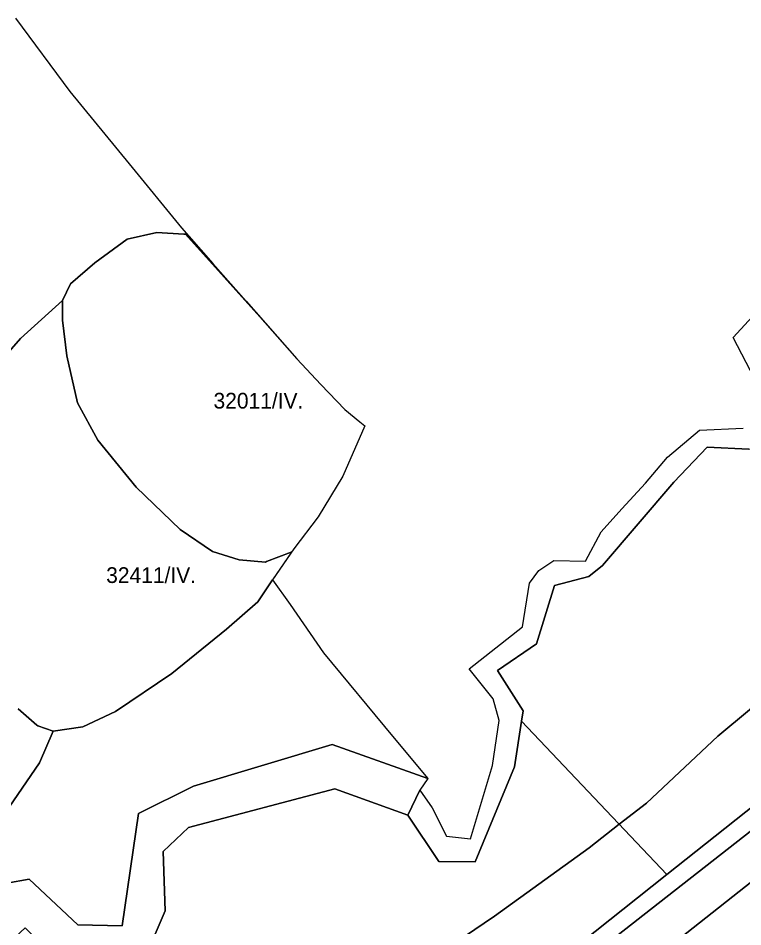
# Model space of a CAD drawing. Extents: x -522079 to -518833, y -1142400 to -1139961.
# Drawn here: x -521596.1 to -521365.3, y -1140523.8 to -1140234.6 of the extents above; entities that cross this region are included whole.
import ezdxf

# ---------------------------------------------------------------- set-up
doc = ezdxf.new("R2010")
doc.units = 0
for name, color, linetype in [('95560013', 7, 'Continuous'), ('95610013', 7, 'Continuous'), ('95630013', 7, 'Continuous'), ('95640013', 7, 'Continuous'), ('95660013', 7, 'Continuous')]:
    doc.layers.add(name, color=color, linetype=linetype)

msp = doc.modelspace()

# ---------------------------------------------------------------- linework, layer by layer
at = {"layer": '95560013'}
msp.add_lwpolyline([(-521596.95, -1140234.61), (-521579.62, -1140257.92), (-521560.73, -1140281.01), (-521544.01, -1140301.33), (-521541.69, -1140303.97), (-521534.06, -1140312.64), (-521523.43, -1140324.72), (-521507.29, -1140343.05), (-521499.72, -1140351.14), (-521492.09, -1140359.13), (-521487.26, -1140363.09), (-521485.71, -1140364.38), (-521492.65, -1140380.39), (-521500.52, -1140393.33), (-521508.32, -1140403.51), (-521515.07, -1140413.37), (-521509.46, -1140421.2), (-521498.88, -1140436.59), (-521476.87, -1140463.06), (-521465.61, -1140476.61), (-521496.06, -1140465.78), (-521540.23, -1140479.04), (-521557.78, -1140487.71), (-521562.91, -1140523.45), (-521577.07, -1140523.11), (-521592.51, -1140508.64), (-521606.9, -1140511.13)], dxfattribs=at)
for points in [[(-521042, -1140261.25), (-521029.36, -1140265.01), (-521071.25, -1140292.13), (-521105.44, -1140313.39), (-521138.04, -1140336), (-521166.55, -1140356.84), (-521170.88, -1140360.01), (-521186.8, -1140371.65), (-521202.24, -1140382.94), (-521262.52, -1140430.5), (-521393.25, -1140533.65), (-521431, -1140563.44), (-521501.14, -1140618.78), (-521510.5, -1140608.85), (-521177.32, -1140348.18), (-521127.62, -1140312.94), (-521125.23, -1140315.3), (-521106.97, -1140303.78), (-521080.73, -1140284.42), (-521065.28, -1140272.43), (-521054.61, -1140266.48)], [(-521309.07, -1140623.96), (-521393.25, -1140533.65), (-521262.52, -1140430.5), (-521152, -1140551.52)]]:
    msp.add_lwpolyline(points, close=True, dxfattribs=at)
at = {"layer": '95610013'}
for points in [[(-521443.44, -1140442.21), (-521430.97, -1140433.67), (-521425.29, -1140415.18), (-521414.4, -1140412.25), (-521409.97, -1140408.74), (-521387.23, -1140382.25), (-521376.68, -1140371.11), (-521363.37, -1140371.78), (-521350.48, -1140368.68), (-521348.98, -1140355.15), (-521360.62, -1140338.49), (-521354.5, -1140332.33), (-521274.04, -1140415.55), (-521389.53, -1140507.12), (-521435.8, -1140458.35), (-521435.3, -1140455)], [(-521389.53, -1140507.12), (-521513.48, -1140605.69), (-521566.82, -1140550.59), (-521584.91, -1140532.83), (-521565.66, -1140535.94), (-521555.6, -1140533.49), (-521549.24, -1140518.67), (-521549.91, -1140499.85), (-521541.79, -1140492.15), (-521495.23, -1140479.84), (-521471.95, -1140488.22), (-521462.16, -1140502.96), (-521450.52, -1140503.04), (-521437.98, -1140472.83), (-521435.8, -1140458.35)]]:
    msp.add_lwpolyline(points, close=True, dxfattribs=at)
at = {"layer": '95630013'}
for points in [[(-521357.5, -1140357.21), (-521368.43, -1140336.25), (-521357.43, -1140324.38)], [(-521363.37, -1140371.78), (-521376.68, -1140371.11), (-521387.23, -1140382.25), (-521409.97, -1140408.74), (-521414.4, -1140412.25), (-521425.29, -1140415.18), (-521430.97, -1140433.67), (-521443.44, -1140442.21), (-521435.3, -1140455), (-521435.8, -1140458.35), (-521437.98, -1140472.83), (-521450.52, -1140503.04), (-521462.16, -1140502.96), (-521471.95, -1140488.22), (-521468.11, -1140480.32), (-521464.21, -1140485.93), (-521459.62, -1140494.93), (-521451.98, -1140495.75), (-521445.06, -1140472.47), (-521442.88, -1140458.09), (-521444.82, -1140451.17), (-521452.48, -1140441.66), (-521435.44, -1140428.3), (-521433.21, -1140414.4), (-521430.32, -1140410.33), (-521425.52, -1140407.15), (-521415.37, -1140407.41), (-521410.38, -1140398.05), (-521403.86, -1140390.75), (-521396.32, -1140382.62), (-521389.35, -1140374.32), (-521379.07, -1140365.7), (-521365.2, -1140365.12)], [(-521606.9, -1140511.13), (-521592.51, -1140508.64), (-521577.07, -1140523.11), (-521562.91, -1140523.45), (-521557.78, -1140487.71), (-521540.23, -1140479.04), (-521496.06, -1140465.78), (-521465.61, -1140476.61), (-521468.11, -1140480.32), (-521471.95, -1140488.22), (-521495.23, -1140479.84), (-521541.79, -1140492.15), (-521549.91, -1140499.85), (-521549.24, -1140518.67), (-521555.6, -1140533.49), (-521565.66, -1140535.94), (-521584.91, -1140532.83), (-521593.79, -1140524.1), (-521596.8, -1140526.87)]]:
    msp.add_lwpolyline(points, dxfattribs=at)
at = {"layer": '95640013'}
msp.add_lwpolyline([(-521245.45, -1140392.88), (-521233.39, -1140383.74), (-521212.85, -1140368.17), (-521190.73, -1140351.49), (-521181.05, -1140344.19), (-521160.13, -1140329.24), (-521148.51, -1140320.94), (-521130.86, -1140309.33), (-521127.62, -1140312.94), (-521177.32, -1140348.18), (-521510.5, -1140608.85), (-521513.48, -1140605.69), (-521389.53, -1140507.12), (-521274.04, -1140415.55), (-521252.22, -1140398.25)], close=True, dxfattribs=at)
at = {"layer": '95660013'}
for points in [[(-521596.95, -1140234.61), (-521579.62, -1140257.92), (-521560.73, -1140281.01), (-521544.01, -1140301.33), (-521541.69, -1140303.97), (-521534.06, -1140312.64), (-521523.43, -1140324.72), (-521519.09, -1140329.65), (-521542.8, -1140303.36), (-521543.3, -1140303.33), (-521551.95, -1140302.78), (-521561.32, -1140304.95), (-521571.66, -1140312.43), (-521579.35, -1140319.18), (-521582, -1140324.49), (-521595.28, -1140336.6), (-521608.32, -1140351.33)], [(-521608.32, -1140351.33), (-521595.28, -1140336.6), (-521582, -1140324.49), (-521582, -1140330.76), (-521580.56, -1140342.09), (-521577.19, -1140357.04), (-521570.7, -1140368.86), (-521558.44, -1140383.81), (-521544.49, -1140397.32), (-521534.16, -1140404.31), (-521525.74, -1140406.96), (-521517.33, -1140407.69), (-521516.94, -1140407.54), (-521509.18, -1140404.57), (-521509, -1140404.5), (-521515.07, -1140413.37), (-521519.72, -1140420.31), (-521529.77, -1140429.03), (-521547.17, -1140443.21), (-521565.11, -1140455.2), (-521575.43, -1140460.11), (-521584.95, -1140461.48), (-521589.84, -1140459.84), (-521590.17, -1140459.55), (-521596.09, -1140454.38)], [(-521357.5, -1140357.21), (-521368.43, -1140336.25), (-521357.43, -1140324.38)], [(-521598.91, -1140485.69), (-521589.25, -1140471.59), (-521584.95, -1140461.48), (-521575.43, -1140460.11), (-521565.11, -1140455.2), (-521547.17, -1140443.21), (-521529.77, -1140429.03), (-521519.72, -1140420.31), (-521515.07, -1140413.37), (-521509.46, -1140421.2), (-521498.88, -1140436.59), (-521476.87, -1140463.06), (-521465.61, -1140476.61), (-521468.11, -1140480.32), (-521464.21, -1140485.93), (-521459.62, -1140494.93), (-521451.98, -1140495.75), (-521445.06, -1140472.47), (-521442.88, -1140458.09), (-521444.82, -1140451.17), (-521452.48, -1140441.66), (-521435.44, -1140428.3), (-521433.21, -1140414.4), (-521430.32, -1140410.33), (-521425.52, -1140407.15), (-521415.37, -1140407.41), (-521410.38, -1140398.05), (-521403.86, -1140390.75), (-521396.32, -1140382.62), (-521389.35, -1140374.32), (-521379.07, -1140365.7), (-521365.2, -1140365.12)], [(-521352.5, -1140445.81), (-521373.25, -1140463.07), (-521396.02, -1140484.39), (-521404.68, -1140491.15), (-521414.24, -1140498.6), (-521444.35, -1140520.43), (-521482.31, -1140546.07)], [(-521482.31, -1140546.07), (-521444.35, -1140520.43), (-521414.24, -1140498.6), (-521404.68, -1140491.15), (-521396.02, -1140484.39), (-521373.25, -1140463.07), (-521352.5, -1140445.81)], [(-521596.09, -1140454.38), (-521590.17, -1140459.55), (-521589.84, -1140459.84), (-521584.95, -1140461.48), (-521589.25, -1140471.59), (-521598.91, -1140485.69)]]:
    msp.add_lwpolyline(points, dxfattribs=at)
msp.add_lwpolyline([(-521487.26, -1140363.09), (-521485.71, -1140364.38), (-521492.65, -1140380.39), (-521500.52, -1140393.33), (-521508.32, -1140403.51), (-521509, -1140404.5), (-521509.18, -1140404.57), (-521516.94, -1140407.54), (-521517.33, -1140407.69), (-521525.74, -1140406.96), (-521534.16, -1140404.31), (-521544.49, -1140397.32), (-521558.44, -1140383.81), (-521570.7, -1140368.86), (-521577.19, -1140357.04), (-521580.56, -1140342.09), (-521582, -1140330.76), (-521582, -1140324.49), (-521579.35, -1140319.18), (-521571.66, -1140312.43), (-521561.32, -1140304.95), (-521551.95, -1140302.78), (-521543.3, -1140303.33), (-521542.8, -1140303.36), (-521519.09, -1140329.65), (-521507.29, -1140343.05), (-521499.72, -1140351.14), (-521492.09, -1140359.13)], close=True, dxfattribs=at)

# ---------------------------------------------------------------- texts
for s, rotation, p in [('32011/IV.', 0, (-521533.86, -1140358.84)), ('32411/IV.', 360, (-521568.04, -1140414.35))]:
    msp.add_text(s, height=5, rotation=rotation, dxfattribs=at).set_placement(p)

doc.saveas('drawing.dxf')
